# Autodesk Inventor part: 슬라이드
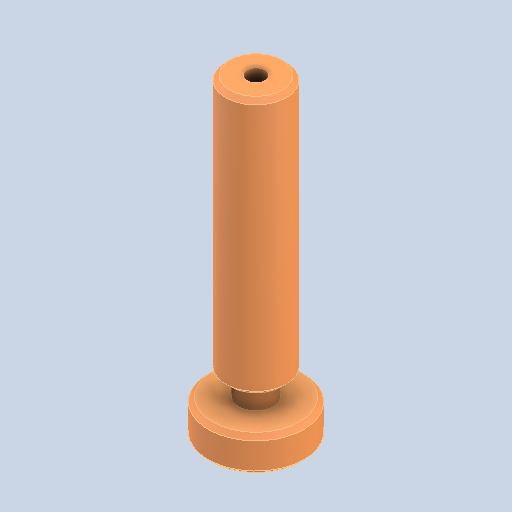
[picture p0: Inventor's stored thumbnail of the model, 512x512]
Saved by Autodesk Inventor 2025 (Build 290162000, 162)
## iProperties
Created: 2024-07
Part Number: 슬라이드
Material: 강철, 연강
Document SubType Name: Modeling
Designer: parkm
Density: 7.86 g/cm^3
Appearance: 기본값
Author: jhkim
Sending System: Autodesk Inventor 2025
Preprocessor: ST-DEVELOPER v20
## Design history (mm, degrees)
feature "솔리드1"
node "솔리드2"
